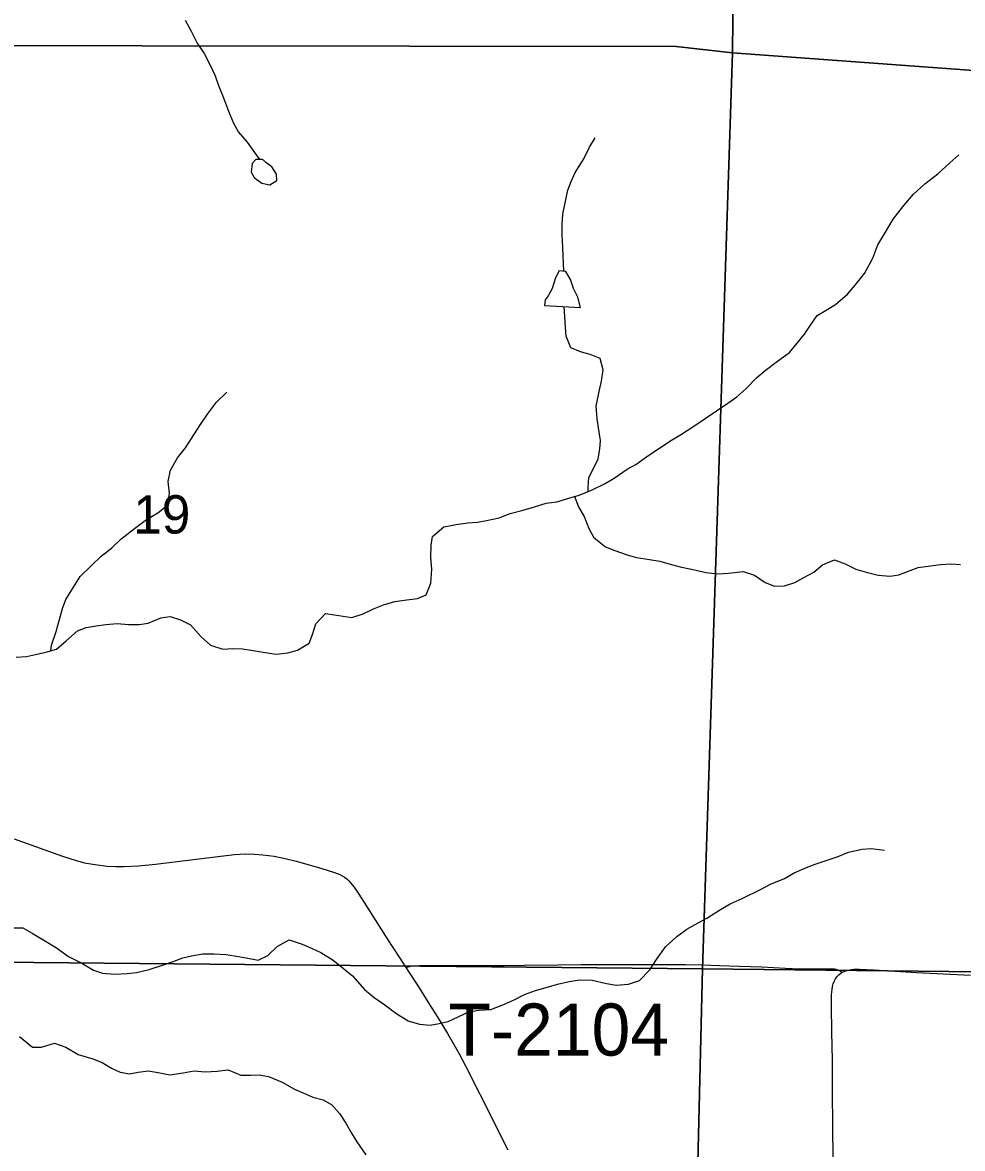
# Model space of a CAD drawing. Extents: x 1874609 to 2204689, y 815661 to 1281160.
# Drawn here: x 2015341 to 2020755, y 1002678 to 1009164 of the extents above; entities that cross this region are included whole.
import ezdxf

# ---------------------------------------------------------------- set-up
doc = ezdxf.new("R2010")
doc.units = 0
for name, color, linetype in [('GM_X_County_Road', 7, 'Continuous'), ('GM_X_Minor_Lake', 7, 'Continuous'), ('GM_X_Minor_River', 7, 'Continuous'), ('GM_X_Section', 7, 'Continuous'), ('GM_X_Section_Text', 7, 'Continuous'), ('GM_X_State_Route', 7, 'Continuous'), ('GM_X_Township_Road', 7, 'Continuous'), ('GM_X_Township_Road_Text', 7, 'Continuous')]:
    doc.layers.add(name, color=color, linetype=linetype)

msp = doc.modelspace()

# ---------------------------------------------------------------- linework, layer by layer
at = {"layer": 'GM_X_County_Road'}
for points in [[(2015293.8, 1004461.6), (2015463.3, 1004400.8), (2015571.5, 1004362.4), (2015649.8, 1004337.1), (2015697.7, 1004324.5), (2015746.3, 1004315.5), (2015828, 1004304.9), (2015877.3, 1004302), (2015926.8, 1004302.3), (2016009, 1004307.1), (2016107.2, 1004316.7), (2016465.4, 1004361.1), (2016563, 1004371.7), (2016628, 1004375.3), (2016676.8, 1004374.3), (2016725.6, 1004370.1), (2016790.4, 1004361.5), (2016854.6, 1004349.2), (2016918, 1004333.7), (2017059.8, 1004292.7), (2017138.2, 1004268.7), (2017168.1, 1004256.8), (2017182.2, 1004249.4), (2017195.6, 1004241), (2017208.4, 1004231.6), (2017220.1, 1004220.7), (2017231.2, 1004209.1), (2017251.6, 1004183.9), (2017279.1, 1004143.6), (2017323.1, 1004074.4), (2017446.3, 1003880.4), (2017535.6, 1003742.7), (2017549.9, 1003720.5)], [(2017549.9, 1003720.5), (2017615.5, 1003618.5), (2017686.1, 1003508), (2017729.4, 1003438.4), (2017788.8, 1003340.2), (2017854.7, 1003227), (2017893.2, 1003154.9), (2018055.2, 1002832.8), (2018113.4, 1002715.2), (2018136.7, 1002671.6)]]:
    msp.add_lwpolyline(points, dxfattribs=at)
at = {"layer": 'GM_X_Minor_Lake'}
for points in [[(2016685.2, 1008374.3), (2016663.1, 1008352.3), (2016658.9, 1008302.2), (2016674.8, 1008272), (2016718.8, 1008239.7), (2016764.9, 1008229.5), (2016805.1, 1008253.4), (2016803.2, 1008291.5), (2016777.3, 1008333.8), (2016743.3, 1008358)], [(2016743.3, 1008358), (2016729, 1008371.3), (2016721.8, 1008374.6), (2016714.6, 1008375.2), (2016685.2, 1008374.3)], [(2018554.4, 1007523.4), (2018540.6, 1007581.6), (2018514.7, 1007631.9), (2018496.9, 1007684.1), (2018471, 1007730.4), (2018432.9, 1007734.6), (2018410.7, 1007694.5), (2018392.4, 1007632.4), (2018368.2, 1007590.4), (2018352.1, 1007566.4), (2018348, 1007534.3)], [(2018348, 1007534.3), (2018554.4, 1007523.4)]]:
    msp.add_lwpolyline(points, dxfattribs=at)
at = {"layer": 'GM_X_Minor_River'}
for points in [[(2016277.2, 1009178.6), (2016313, 1009114.2), (2016346.8, 1009045.8), (2016386.7, 1008985.5), (2016424.6, 1008915.1), (2016450.4, 1008856.8), (2016470.3, 1008800.5), (2016498.1, 1008730.2), (2016527.9, 1008653.8), (2016555.7, 1008583.5), (2016585.6, 1008533.2), (2016635.5, 1008474.8), (2016705.7, 1008374.9)], [(2018459.5, 1007731.7), (2018453.4, 1007866.9), (2018449.7, 1007943.1), (2018449.9, 1008003.3), (2018454.1, 1008059.5), (2018464.3, 1008115.6), (2018482.7, 1008197.8), (2018500.9, 1008247.8), (2018525.1, 1008299.9), (2018573.5, 1008379.9), (2018607.8, 1008446), (2018640.1, 1008500)], [(2015657.3, 1005660.5), (2015707.5, 1005680.3), (2015765.6, 1005688.1), (2015821.8, 1005695.8), (2015885.9, 1005701.6), (2015952.1, 1005697.3), (2016012.2, 1005697), (2016064.3, 1005704.8), (2016138.6, 1005734.6), (2016190.8, 1005742.4), (2016250.8, 1005724), (2016308.9, 1005695.7), (2016370.8, 1005625.2), (2016424.7, 1005576.8), (2016494.8, 1005554.4), (2016552.9, 1005558.2), (2016609, 1005555.9), (2016669.1, 1005547.6), (2016739.3, 1005535.3), (2016801.4, 1005525), (2016869.5, 1005532.7), (2016925.7, 1005548.5), (2016992, 1005588.3), (2017012.2, 1005638.4), (2017030.5, 1005700.5), (2017086.8, 1005760.4), (2017138.9, 1005752.2), (2017237.1, 1005737.7), (2017303.3, 1005757.5), (2017363.6, 1005787.3), (2017419.8, 1005809.1), (2017486, 1005828.9), (2017540.1, 1005836.7), (2017616.4, 1005846.4), (2017666.5, 1005868.2), (2017692.8, 1005934.3), (2017699.1, 1006014.5), (2017693.4, 1006082.8), (2017695.6, 1006153), (2017701.8, 1006203.1), (2017768.2, 1006259), (2017838.4, 1006272.7), (2017906.5, 1006282.4), (2017962.7, 1006286.2), (2018012.8, 1006296), (2018087.1, 1006311.7), (2018149.3, 1006335.5), (2018217.5, 1006353.3), (2018289.7, 1006375), (2018358, 1006394.8), (2018418.1, 1006402.5), (2018488.4, 1006424.3), (2018546.6, 1006442.1), (2018618.8, 1006469.8), (2018697.1, 1006509.6), (2018749.4, 1006539.5), (2018823.7, 1006591.3), (2018873.9, 1006619.2), (2018942.3, 1006669), (2019016.6, 1006716.8), (2019068.8, 1006752.7), (2019137.1, 1006792.5), (2019207.5, 1006838.4), (2019279.8, 1006886.2), (2019338.1, 1006928.1), (2019404.4, 1006971.9), (2019454.6, 1007007.8), (2019506.9, 1007053.7), (2019569.3, 1007117.6), (2019619.5, 1007159.5), (2019689.9, 1007213.4), (2019758.2, 1007263.3), (2019802.5, 1007317.2), (2019844.8, 1007369.2), (2019879.1, 1007421.2), (2019917.3, 1007477.2), (2019969.6, 1007507.1), (2020023.8, 1007540.9), (2020092.2, 1007598.8), (2020136.5, 1007650.8), (2020190.8, 1007718.7), (2020239.2, 1007806.8), (2020267.6, 1007882.9), (2020305.9, 1007946.9), (2020356.3, 1008031), (2020416.7, 1008111), (2020473.1, 1008174.9), (2020537.4, 1008234.8), (2020613.8, 1008292.7), (2020682.2, 1008356.5), (2020734.5, 1008402.4)], [(2018599, 1006462.2), (2018598.8, 1006488), (2018603.1, 1006542.2), (2018657.6, 1006650.2), (2018665.8, 1006706.4), (2018670, 1006756.5), (2018658.2, 1006828.8), (2018650.4, 1006881), (2018644.6, 1006955.2), (2018662.9, 1007039.4), (2018675.2, 1007097.5), (2018685.4, 1007163.7), (2018667.6, 1007228), (2018611.6, 1007252.3), (2018555.5, 1007266.6), (2018499.5, 1007290.9), (2018471.6, 1007357.2), (2018467.8, 1007409.4), (2018461.5, 1007528.3)], [(2015504.6, 1005545.2), (2015508.6, 1005576.9), (2015535, 1005657), (2015553.3, 1005725.1), (2015571.5, 1005789.2), (2015589.8, 1005841.3), (2015634.1, 1005911.3), (2015672.4, 1005973.4), (2015738.8, 1006037.3), (2015795.1, 1006091.2), (2015853.4, 1006137.1), (2015907.7, 1006189), (2015986.1, 1006248.8), (2016054.4, 1006300.7), (2016120.7, 1006340.5), (2016177, 1006384.4), (2016187.3, 1006452.6), (2016179.5, 1006520.8), (2016193.8, 1006584.9), (2016234.1, 1006657), (2016280.4, 1006715), (2016314.7, 1006769), (2016363.1, 1006843), (2016407.4, 1006909), (2016457.7, 1006977), (2016518.1, 1007034.9)], [(2018519.8, 1006433.9), (2018546.3, 1006369.9), (2018576.2, 1006319.6), (2018604, 1006249.2), (2018631.9, 1006196.9), (2018699.9, 1006144.5), (2018751.9, 1006122.2), (2018824, 1006097.8), (2018878, 1006083.5), (2018952.2, 1006071.2), (2019012.3, 1006060.8), (2019072.3, 1006044.5), (2019128.4, 1006028.2), (2019220.6, 1006009.8), (2019276.6, 1005995.5), (2019346.8, 1005989.2), (2019406.9, 1005992.9), (2019491.1, 1006002.6), (2019557.2, 1005980.2), (2019619.2, 1005937.8), (2019673.2, 1005917.5), (2019729.4, 1005919.2), (2019789.6, 1005939), (2019841.8, 1005966.9), (2019898.1, 1005998.7), (2019948.3, 1006040.7), (2020018.6, 1006068.4), (2020078.6, 1006046.1), (2020140.7, 1006015.7), (2020208.7, 1005995.4), (2020268.8, 1005981), (2020339, 1005974.7), (2020389.1, 1005982.5), (2020439.3, 1006002.4), (2020499.5, 1006024.2), (2020571.7, 1006033.9), (2020627.9, 1006041.7), (2020692, 1006045.4), (2020744.1, 1006043.2)], [(2015303.9, 1005507.6), (2015364.1, 1005513.3), (2015416.2, 1005523.1), (2015476.4, 1005536.9), (2015536.6, 1005554.7), (2015592.9, 1005602.6), (2015657.3, 1005660.5)], [(2019785.6, 1004265.9), (2019855.9, 1004297.7), (2019906.1, 1004315.5), (2019964.3, 1004335.3), (2020032.5, 1004359.1), (2020098.8, 1004384.9), (2020177, 1004402.6), (2020229.1, 1004406.4), (2020305.3, 1004396)], [(2015270.3, 1003948.9), (2015342.5, 1003948.6), (2015396.5, 1003918.3), (2015474.5, 1003871.8), (2015536.5, 1003833.4), (2015606.5, 1003784.9), (2015682.5, 1003746.5), (2015750.6, 1003706), (2015802.6, 1003687.8), (2015872.7, 1003683.4), (2015944.9, 1003687.1), (2015997.1, 1003692.9), (2016071.3, 1003708.6), (2016147.5, 1003734.4), (2016213.8, 1003758.2), (2016264, 1003776), (2016314.1, 1003787.8), (2016380.3, 1003799.5), (2016444.4, 1003799.2), (2016512.6, 1003794.9), (2016562.7, 1003788.7), (2016628.8, 1003776.4), (2016698.9, 1003764), (2016755.1, 1003789.8), (2016807.4, 1003841.8), (2016877.7, 1003879.6), (2016951.8, 1003855.2), (2017009.8, 1003830.8), (2017059.9, 1003806.6), (2017129.9, 1003764.1), (2017189.8, 1003715.7), (2017241.8, 1003673.3), (2017311.7, 1003594.8), (2017367.6, 1003548.4), (2017427.6, 1003506), (2017491.6, 1003457.6), (2017561.6, 1003413.1), (2017627.7, 1003394.8), (2017689.8, 1003388.5), (2017741.9, 1003398.3), (2017792.1, 1003410.1), (2017850.3, 1003435.9), (2017912.6, 1003465.7), (2017968.7, 1003475.5), (2018038.9, 1003479.2), (2018107.1, 1003505), (2018169.4, 1003532.8), (2018231.6, 1003564.6), (2018295.9, 1003588.4), (2018370.1, 1003610.2), (2018422.3, 1003624), (2018490.5, 1003639.7), (2018548.6, 1003649.5), (2018622.8, 1003647.2), (2018704.9, 1003628.7), (2018761, 1003618.4), (2018831.2, 1003624.2), (2018895.4, 1003645.9), (2018953.8, 1003707.9), (2018992.1, 1003767.9), (2019044.4, 1003839.9), (2019110.8, 1003899.8), (2019167.1, 1003941.6), (2019233.4, 1003977.5), (2019283.6, 1004005.3), (2019361.9, 1004055.1), (2019416.2, 1004087), (2019486.4, 1004118.8), (2019594.9, 1004172.5), (2019649.1, 1004200.3), (2019729.4, 1004234.1), (2019785.6, 1004265.9)], [(2015324.2, 1003322.8), (2015398.2, 1003262.2), (2015450.3, 1003262), (2015524.5, 1003285.8), (2015590.6, 1003261.4), (2015662.6, 1003218.9), (2015746.7, 1003194.5), (2015800.8, 1003174.2), (2015852.8, 1003141.9), (2015902.8, 1003117.5), (2015956.9, 1003109.3), (2016007, 1003117.1), (2016067.2, 1003124.8), (2016131.3, 1003114.5), (2016189.4, 1003102.2), (2016265.6, 1003113.9), (2016329.8, 1003125.7), (2016393.9, 1003119.4), (2016462.1, 1003123.1), (2016526.3, 1003130.8), (2016598.3, 1003100.4), (2016654.4, 1003100.2), (2016704.6, 1003102), (2016758.6, 1003093.7), (2016836.7, 1003061.2), (2016908.7, 1003020.8), (2016960.8, 1002996.5), (2017012.8, 1002974.2), (2017072.9, 1002957.9), (2017122.9, 1002929.6), (2017166.8, 1002879.2), (2017202.7, 1002824.9), (2017236.6, 1002766.6), (2017266.4, 1002716.3), (2017318.3, 1002641.8)]]:
    msp.add_lwpolyline(points, dxfattribs=at)
at = {"layer": 'GM_X_Section'}
for points in [[(2012933.5, 1014271.1), (2019482.8, 1014226.8), (2019429.8, 1008990.1), (2019105.5, 1009025.5), (2012952.5, 1009034.6), (2012954.3, 1009164.7)], [(2019482.8, 1014226.8), (2024807.5, 1014199.9), (2024699.2, 1008602.9), (2019429.8, 1008990.1)], [(2019429.8, 1008990.1), (2019258.7, 1003713.2), (2012971.6, 1003772.1), (2012981.3, 1003882.2), (2012952.5, 1009034.6), (2019105.5, 1009025.5)], [(2024699.2, 1008602.9), (2024581.4, 1003656.3), (2019258.7, 1003713.2), (2019429.8, 1008990.1)], [(2012971.6, 1003772.1), (2019258.7, 1003713.2), (2019130.9, 998442.8), (2013021.7, 998539.9)], [(2024581.4, 1003656.3), (2024501.5, 998386.1), (2019130.9, 998442.8), (2019258.7, 1003713.2)]]:
    msp.add_lwpolyline(points, close=True, dxfattribs=at)
at = {"layer": 'GM_X_State_Route'}
msp.add_lwpolyline([(2020011.4, 1002579.1), (2020009.3, 1002759.6), (2020006.7, 1003054.9), (2020006, 1003186.1), (2020003.4, 1003350), (2020000.7, 1003497.3), (2020001, 1003562.7), (2020003.9, 1003595), (2020006.8, 1003610.7), (2020010.8, 1003626.3), (2020016.2, 1003641), (2020023.2, 1003655.1), (2020031.9, 1003667.7), (2020042.1, 1003679.1), (2020054.4, 1003688.5), (2020062.4, 1003693.3), (2020067.7, 1003696.4), (2020082.4, 1003702.1), (2020097.7, 1003706.5), (2020113.4, 1003709.1), (2020129.6, 1003710.8), (2020162.2, 1003711.3), (2020243.9, 1003707.1), (2020489.6, 1003691.4), (2020801.1, 1003677.7)], dxfattribs=at)
at = {"layer": 'GM_X_Township_Road'}
msp.add_lwpolyline([(2017549.9, 1003720.5), (2017570.8, 1003726.9), (2017582.4, 1003729.8), (2017592.4, 1003731), (2017625.1, 1003732.7), (2017674.1, 1003733), (2017788.6, 1003732.3), (2018115.6, 1003733), (2018230.1, 1003733.7), (2018426.5, 1003736.9), (2018559, 1003737.3), (2018620.7, 1003737.4), (2018757.9, 1003737.8), (2018902, 1003738.2), (2018965.4, 1003738.4), (2019063.3, 1003738.1), (2019159.3, 1003737.8), (2019257.2, 1003736.1), (2019354.9, 1003732.5), (2019469.1, 1003729.4), (2019599.5, 1003724.1), (2019733.1, 1003717), (2019817, 1003712.7), (2019975.4, 1003713.1), (2020011.3, 1003713.1), (2020018.9, 1003712.8), (2020026, 1003711.4), (2020036, 1003707.6), (2020044.6, 1003703.2), (2020052.2, 1003699), (2020062.4, 1003693.3)], dxfattribs=at)

# ---------------------------------------------------------------- texts
at = {"layer": 'GM_X_Section_Text'}
msp.add_text('19', height=221, rotation=0.00001, dxfattribs=at).set_placement((2015979, 1006220.5))
at = {"layer": 'GM_X_Township_Road_Text'}
msp.add_text('T-2104', height=300, rotation=0.00001, dxfattribs=at).set_placement((2017794, 1003213.5))

doc.saveas('drawing.dxf')
